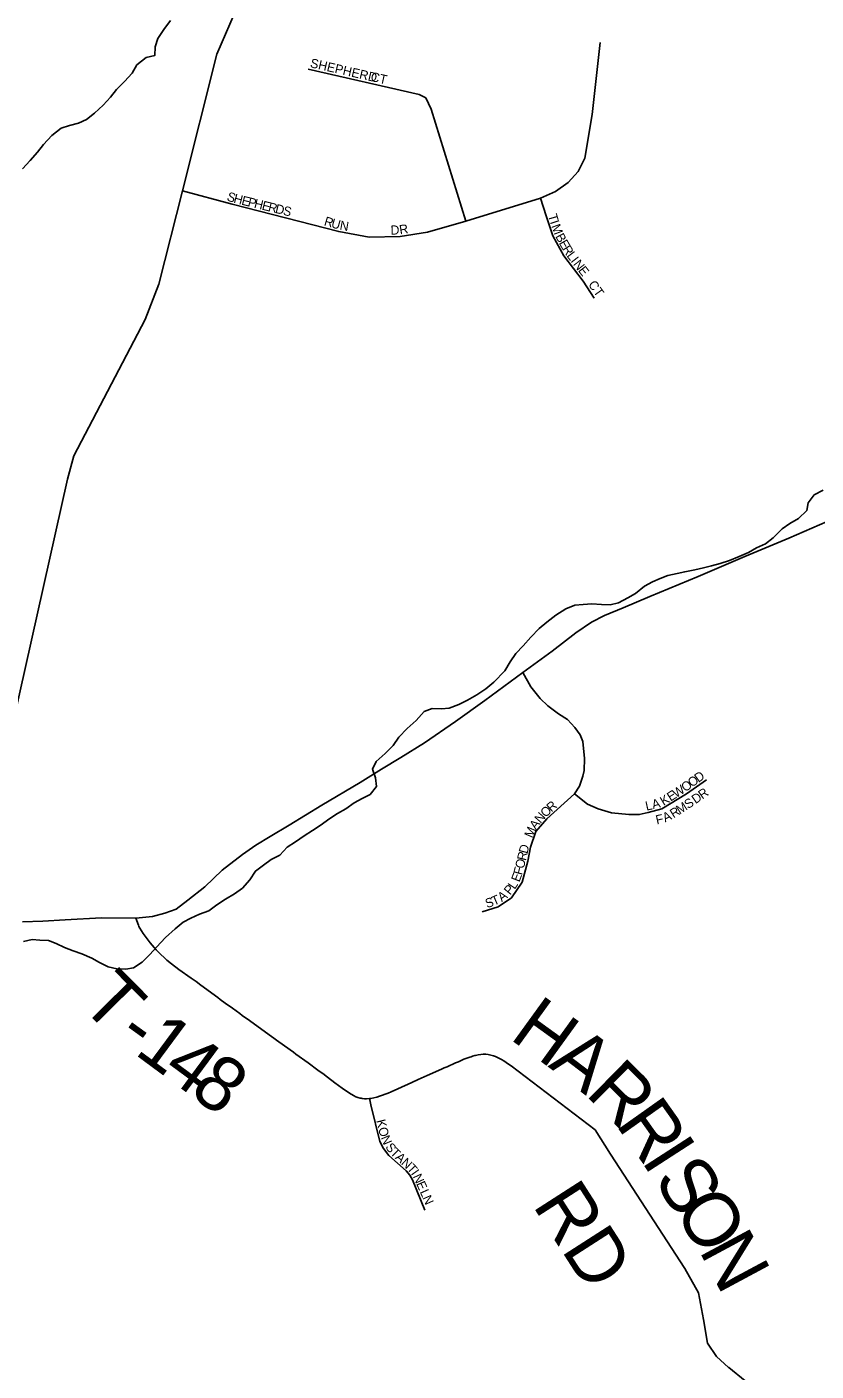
# Model space of a CAD drawing. Extents: x 1310247 to 1664935, y 284496 to 704931.
# Drawn here: x 1479622 to 1483933, y 468897 to 476239 of the extents above; entities that cross this region are included whole.
import ezdxf

# ---------------------------------------------------------------- set-up
doc = ezdxf.new("R2010")
doc.units = 0
for name, color, linetype in [('GM_P_State_Location', 7, 'Continuous'), ('GM_X_County_Subdivision_Text', 7, 'Continuous'), ('GM_X_Interstate_Shield', 7, 'Continuous'), ('GM_X_Minor_River_Text', 7, 'Continuous'), ('GM_X_State_Location', 7, 'Continuous'), ('GM_X_Township_Subdivision', 7, 'Continuous')]:
    doc.layers.add(name, color=color, linetype=linetype)

msp = doc.modelspace()

# ---------------------------------------------------------------- linework, layer by layer
at = {"layer": 'GM_X_County_Subdivision_Text'}
for points in [[(1479484, 472137), (1479515.1, 472303.6), (1479844.5, 473768.3), (1479878, 473895.7), (1480268.6, 474641.3), (1480341.8, 474833.8), (1480471, 475344.6), (1480659.7, 476090.4), (1480777.2, 476364), (1480815.6, 476443.5), (1480857.2, 476514.8), (1480989.7, 476655.6), (1481069.6, 476811.5), (1481210, 477120.4), (1481333.2, 477382.5), (1481503.4, 477769.2), (1481600.6, 478094.7), (1481705, 478561.1), (1481820.9, 478926.9), (1481953.6, 479248.2), (1482508.1, 480456.5)], [(1480216.1, 471372), (1480230.7, 471333.5), (1480233.4, 471326.5), (1480238.3, 471317.3), (1480257, 471288), (1480296.1, 471236.2), (1480306.6, 471223.5), (1480317.2, 471211), (1480328.1, 471198.7), (1480339.3, 471186.7), (1480387.1, 471141.8), (1480412.5, 471121.1), (1480451.8, 471091.5), (1480518.8, 471043.8), (1480545.6, 471024.6), (1480572.2, 471005.4), (1480664.9, 470937.1), (1480678.2, 470927.3), (1480704.7, 470907.9), (1480744.8, 470879), (1480784.7, 470850), (1480798, 470840.4), (1480811.4, 470830.7), (1480824.7, 470821.1), (1480957.9, 470724.6), (1480971.2, 470715), (1480977.9, 470710.2), (1480984.6, 470705.3), (1480997.9, 470695.7), (1481078.4, 470638.6), (1481091.8, 470629), (1481158.4, 470580.7), (1481211.4, 470541.7), (1481224.7, 470532), (1481237.9, 470522.2), (1481264.2, 470502.3), (1481303.6, 470472.3), (1481343.4, 470443.1), (1481384.2, 470415.5), (1481406.2, 470402), (1481418, 470396.1), (1481430.2, 470391.4), (1481441.6, 470388.3), (1481447.5, 470387.3), (1481453.3, 470386.3), (1481465.3, 470385.3), (1481477.6, 470385.3), (1481493.3, 470386.8), (1481500, 470386.9), (1481516.5, 470389.8), (1481532.7, 470393.7), (1481548.8, 470398.5), (1481595.9, 470415.9), (1481611.4, 470422.3), (1481648.3, 470439.2), (1481724.7, 470474.5), (1481758.7, 470490.1), (1481807.9, 470512.7), (1481886.8, 470546.3), (1481902, 470553.2), (1481917.3, 470560.1), (1481932.7, 470567), (1481948, 470573.9), (1481963.3, 470580.7), (1481978.6, 470587.5), (1482009.5, 470600.5), (1482025.2, 470606.6), (1482040.9, 470612.2), (1482048.9, 470614.8), (1482056.8, 470617.3), (1482068.7, 470620.6), (1482073, 470621.7), (1482087.6, 470625.7), (1482101.3, 470627.4), (1482114.8, 470628.1), (1482128.3, 470627.7), (1482141.6, 470626.2), (1482155.5, 470623.5), (1482170.4, 470619.2), (1482181.8, 470615.1), (1482193.1, 470610.3), (1482204, 470604.9), (1482214.7, 470598.7), (1482226.3, 470592.3), (1482253.4, 470574.1), (1482266.8, 470564.7), (1482726.3, 470215.2), (1482810.1, 470082.2), (1483215.7, 469458.2), (1483291.2, 469325.2), (1483317.5, 469179), (1483338.8, 469049.3), (1483389.7, 468977), (1483454.4, 468917.3)], [(1483454.4, 468917.3), (1483455.4, 468916.3), (1483901.6, 468552.3)]]:
    msp.add_lwpolyline(points, dxfattribs=at)
at = {"layer": 'GM_X_Interstate_Shield'}
msp.add_lwpolyline([(1479598.2, 471351.5), (1479708.2, 471354.8), (1479831.4, 471363), (1480030.1, 471372.8), (1480216.1, 471372), (1480307.1, 471381.2), (1480375.8, 471398.7), (1480436.5, 471420.3), (1480501.2, 471470.1), (1480594.2, 471542.9), (1480688.5, 471633.2), (1480799.1, 471718.2), (1480871.9, 471769.4), (1480951.4, 471817.9), (1481053.8, 471879.9), (1481233.1, 471989), (1481442, 472113.1), (1481559.3, 472184.5), (1481664.4, 472249.2), (1481793.8, 472328.7), (1481962.3, 472446), (1482124, 472560.5), (1482331, 472713.1), (1482490.6, 472830.1), (1482619.8, 472930.1), (1482706.5, 472988.8), (1482776.3, 473025.1), (1482878.3, 473065.7), (1483025.1, 473128.5), (1483289.1, 473237.5), (1483543.4, 473346.5), (1483783.7, 473447.1), (1483993.3, 473537.9)], dxfattribs=at)
at = {"layer": 'GM_X_Minor_River_Text'}
for points in [[(1480405.4, 476273.4), (1480370.5, 476225.9), (1480337.6, 476176.3), (1480322.8, 476130.4), (1480319.9, 476082.3), (1480273.6, 476073), (1480222.8, 476031.7), (1480196, 475986), (1480155.1, 475940.6), (1480112.2, 475897.1), (1480079.4, 475855.5), (1480038.6, 475812.1), (1479991.7, 475768.7), (1479947, 475733.3), (1479904.5, 475714), (1479854.2, 475700.7), (1479809.8, 475685.4), (1479759, 475646.1), (1479712, 475596.7), (1479679.2, 475555.1)], [(1479679.2, 475555.1), (1479640.3, 475509.6), (1479597.4, 475464.2)], [(1483971.5, 473708.2), (1483922.9, 473682.9), (1483890.1, 473639.3), (1483881.4, 473597.4), (1483836.5, 473554), (1483789.9, 473526.6), (1483747.3, 473497.2), (1483698.3, 473447.9), (1483655.6, 473416.5), (1483607.1, 473393.2), (1483564.5, 473367.8), (1483512, 473346.6), (1483459.5, 473325.4), (1483409.1, 473308.1), (1483360.7, 473294.8), (1483318.4, 473285.5), (1483270.1, 473274.2), (1483215.7, 473263.1), (1483173.5, 473253.7), (1483123.1, 473242.5), (1483080.7, 473227.1), (1483038.3, 473207.7), (1482995.7, 473184.4), (1482946.9, 473145), (1482904.4, 473121.6), (1482853.8, 473094.4), (1482807.5, 473083.1), (1482761.3, 473083.8), (1482707.3, 473088.7), (1482661.1, 473085.4), (1482614.8, 473080.1), (1482566.4, 473060.8), (1482511.6, 473025.6), (1482462.8, 472988.3), (1482420.1, 472952.9), (1482375.2, 472905.5), (1482332.3, 472858), (1482293.4, 472816.5), (1482262.6, 472770.9), (1482231.7, 472721.3), (1482172.5, 472660.1), (1482129.7, 472624.7), (1482079, 472591.4), (1482028.4, 472562.1), (1481981.8, 472538.8), (1481929.3, 472517.6), (1481887.2, 472514.2), (1481835, 472517.1), (1481792.6, 472499.7), (1481747.7, 472450.3), (1481698.8, 472406.9), (1481653.8, 472359.5), (1481623, 472313.9), (1481578.1, 472270.5), (1481529.3, 472227.2), (1481510.5, 472185.3), (1481525.7, 472137), (1481531, 472090.8), (1481496.1, 472047.2), (1481453.6, 472025.8), (1481409.1, 472000.5), (1481364.4, 471969.1), (1481317.9, 471943.8), (1481271.2, 471912.5), (1481228.5, 471881), (1481181.9, 471849.7)], [(1481181.9, 471849.7), (1481137.2, 471820.3), (1481088.6, 471789), (1481043.9, 471759.7), (1481003.1, 471716.2), (1480956.5, 471690.9), (1480913.9, 471661.5), (1480871.2, 471628.1), (1480840.3, 471580.5), (1480799.4, 471535), (1480756.8, 471503.6), (1480706.1, 471474.3), (1480659.5, 471445), (1480614.8, 471411.6), (1480564.3, 471392.3), (1480517.8, 471371), (1480475.3, 471349.6), (1480432.6, 471312.2), (1480379.6, 471265), (1480330.6, 471213.6), (1480293.8, 471172.1), (1480251, 471130.6), (1480204.3, 471099.3), (1480162.1, 471092), (1480114, 471094.7), (1480066, 471105.5), (1480018.2, 471128.3), (1479976.5, 471153.1), (1479922.7, 471176), (1479874.9, 471192.8), (1479827, 471211.6), (1479781.2, 471232.4), (1479739.4, 471249.1), (1479693.3, 471251.8), (1479651.2, 471254.5), (1479602.9, 471243.2)]]:
    msp.add_lwpolyline(points, dxfattribs=at)
at = {"layer": 'GM_X_State_Location'}
for points in [[(1480471, 475344.6), (1480743.3, 475271.8), (1481325.1, 475121.1), (1481492, 475091), (1481660, 475094.6), (1481810.7, 475118.5), (1482020.4, 475179.1), (1482427.2, 475304.4), (1482509.7, 475340.2), (1482579.4, 475388.7), (1482633.1, 475449.7), (1482669.6, 475522.8), (1482708.8, 475760.8), (1482752.8, 476154.9)], [(1481158.8, 476008), (1481764.2, 475869.9), (1481801.4, 475851.3), (1481830.6, 475790.3), (1482020.4, 475179.1)], [(1482721.1, 474756.9), (1482659.8, 474850.5), (1482555.5, 474988.2), (1482494.1, 475099), (1482457.6, 475206.5), (1482427.2, 475304.4)], [(1482109.5, 471405.5), (1482196.3, 471433.7), (1482269.1, 471482.9), (1482327.7, 471567.4), (1482358.3, 471682.4), (1482372.3, 471759.9), (1482402.8, 471844.3), (1482438, 471886.6), (1482461.5, 471914.7), (1482614, 472050.5), (1482640.1, 472091.4), (1482658.6, 472147.1), (1482665.9, 472177.7), (1482668, 472243.3), (1482659.4, 472336.1), (1482643.9, 472372.6), (1482615.1, 472412.4), (1482575.3, 472455.6), (1482526.6, 472487.7), (1482466.9, 472531.9), (1482424.9, 472571.7), (1482374, 472634.8), (1482331, 472713.1)], [(1483334.5, 472126), (1483224.2, 472050.9), (1483090.4, 471968.7), (1483016, 471948.6), (1482966.4, 471936.7), (1482909.8, 471936.7), (1482815.4, 471946.5), (1482742.1, 471968.1), (1482683.4, 471994.7), (1482614, 472050.5)], [(1481795, 469776.3), (1481728, 469942.7), (1481714.3, 469967.2), (1481693.9, 469991), (1481599.6, 470075.1), (1481570.6, 470113.1), (1481549, 470151.8), (1481500.6, 470352.4), (1481495.1, 470378.4), (1481493.3, 470386.8)]]:
    msp.add_lwpolyline(points, dxfattribs=at)

# ---------------------------------------------------------------- texts
at = {"layer": 'GM_P_State_Location'}
for s, rotation, p in [('SHEPHERD', 347.12288, (1481166.3, 476019.4)), ('CT', 347.47891, (1481496.2, 475944.6)), ('S', 340.84792, (1480710.2, 475292.9)), ('H', 345.32556, (1480747.6, 475280.1)), ('E', 346.35024, (1480791.1, 475268.8)), ('P', 346.34806, (1480825.3, 475260.4)), ('H', 346.34018, (1480859.5, 475252.1)), ('E', 346.36605, (1480902.3, 475241.7)), ('R', 346.34655, (1480936.5, 475233.4)), ('D', 346.35488, (1480975, 475224.1)), ('S', 346.36605, (1481017.7, 475213.7)), ('R', 343.45425, (1481241.7, 475156.8)), ('U', 344.21664, (1481280.4, 475145.4)), ('N', 350.1056, (1481328.1, 475132.2)), ('T', 285.97167, (1482467.7, 475210.2)), ('I', 288.34175, (1482478.1, 475174.2)), ('D', 1.28954, (1481608.9, 475104.4)), ('R', 9.08032, (1481660.2, 475106.1)), ('M', 290.24995, (1482485.6, 475151.7)), ('B', 298.2136, (1482506.9, 475095.3)), ('E', 299.45512, (1482526.2, 475059.4)), ('R', 301.16077, (1482544.3, 475027.4)), ('L', 307.0217, (1482567.9, 474988.9)), ('I', 308.10617, (1482589.7, 474960)), ('N', 308.14137, (1482603.3, 474942.7)), ('E', 308.15413, (1482630.5, 474908.1)), ('CT', 305.54359, (1482685.5, 474832.1)), ('D', 35.775, (1483290.3, 472109.9)), ('W', 32.72627, (1483168, 472026.3)), ('O', 35.16478, (1483218.1, 472058.5)), ('O', 35.74343, (1483254.5, 472084.2)), ('A', 15.00184, (1483042.9, 471966.3)), ('K', 31.39748, (1483099.7, 471983.9)), ('E', 32.3874, (1483138, 472007.3)), ('S', 33.56901, (1483233.4, 471966)), ('D', 34.74596, (1483274.6, 471993.5)), ('R', 35.40555, (1483311.3, 472018.9)), ('N', 49.4556, (1482427.6, 471886.1)), ('O', 43.31486, (1482455.2, 471918.5)), ('R', 41.64967, (1482487, 471948.4)), ('L', 12.27986, (1483006, 471958.2)), ('A', 24.863, (1483108.1, 471894.2)), ('R', 31.87805, (1483153.8, 471915.9)), ('M', 32.46346, (1483188, 471937.1)), ('M', 66.8014, (1482382.5, 471805.8)), ('A', 53.07765, (1482401.7, 471851.6)), ('F', 12.67105, (1483062.7, 471882.8)), ('R', 77.00071, (1482347, 471682.3)), ('D', 75.61914, (1482355.8, 471720.5)), ('F', 74.93313, (1482326.2, 471603.8)), ('O', 75.26817, (1482335.4, 471638.1)), ('E', 68.69764, (1482311.5, 471565.4)), ('A', 36.20946, (1482215.7, 471458.5)), ('P', 51.26513, (1482261.5, 471494.4)), ('L', 55.9865, (1482286.2, 471525.5)), ('S', 17.94245, (1482134.5, 471425.8)), ('T', 23.41808, (1482172.8, 471438.5)), ('K', 283.97264, (1481529.8, 470265.9)), ('O', 283.97264, (1481540.4, 470223.2)), ('N', 292.90401, (1481553.7, 470172.4)), ('S', 307.00376, (1481577.5, 470120.3)), ('T', 315.08314, (1481603.8, 470086.4)), ('A', 317.50223, (1481630.4, 470060)), ('N', 317.74154, (1481663, 470030.1)), ('T', 312.25531, (1481694.7, 470001.4)), ('I', 305.49703, (1481717.3, 469976.5)), ('N', 294.81484, (1481728.9, 469960.8)), ('E', 294.03463, (1481747.3, 469921)), ('L', 293.9736, (1481767, 469876.8)), ('N', 293.94474, (1481781.3, 469844.6))]:
    msp.add_text(s, height=50, rotation=rotation, dxfattribs=at).set_placement(p)
at = {"layer": 'GM_X_Township_Subdivision'}
for s, rotation, p in [('T', 314.59091, (1479905.1, 470900.4)), ('H', 324.11805, (1482252.3, 470715.8)), ('-', 324.19061, (1480104.2, 470704.9)), ('1', 323.50166, (1480203.3, 470633.4)), ('A', 322.66818, (1482464.6, 470562.3)), ('4', 323.54242, (1480352.1, 470523.3)), ('8', 323.69175, (1480501.4, 470413.1)), ('R', 315.55197, (1482667.1, 470408.6)), ('R', 305.30856, (1482833.8, 470246.8)), ('I', 302.86092, (1482974.3, 470048.6)), ('S', 302.83344, (1483041.2, 469945.1)), ('RD', 302.73523, (1482380.4, 469804.6)), ('O', 302.63827, (1483150.8, 469775.3)), ('N', 298.21392, (1483290, 469558.2))]:
    msp.add_text(s, height=300, rotation=rotation, dxfattribs=at).set_placement(p)

doc.saveas('drawing.dxf')
